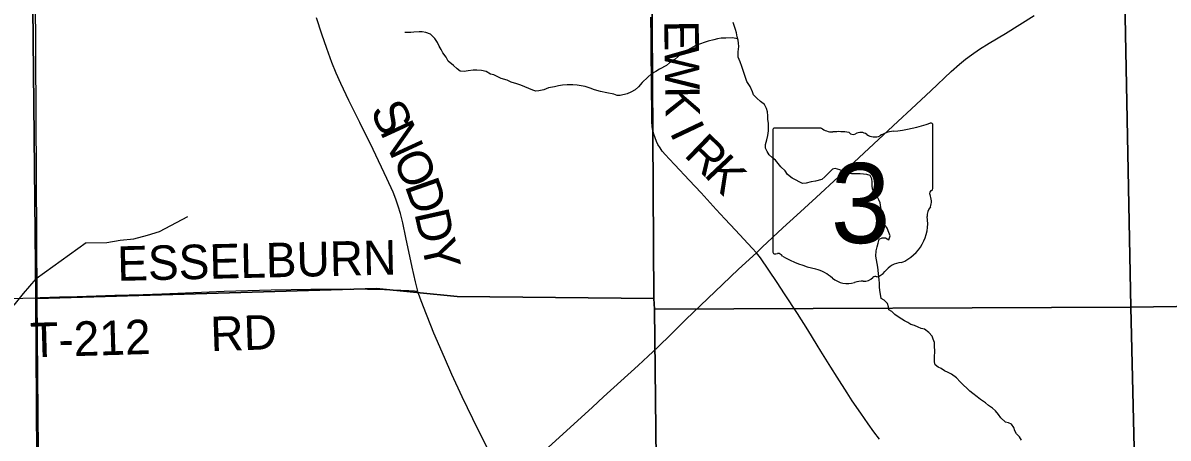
# Model space of a CAD drawing. Extents: x 0 to 34, y 0 to 22.
# Drawn here: x 2.612 to 4.5, y 16.137 to 16.821 of the extents above; entities that cross this region are included whole.
import ezdxf

# ---------------------------------------------------------------- set-up
doc = ezdxf.new("R2010")
doc.units = 0
for name, color, linetype in [('Default', 7, 'Continuous'), ('GM_X_County_Road', 7, 'Continuous'), ('GM_X_County_Road_Text', 7, 'Continuous'), ('GM_X_Minor_River', 7, 'Continuous'), ('GM_X_Section', 7, 'Continuous'), ('GM_X_State_Location', 7, 'Continuous'), ('GM_X_State_Route', 7, 'Continuous'), ('GM_X_State_Shield', 7, 'Continuous'), ('GM_X_Township_Road', 7, 'Continuous'), ('GM_X_Township_Road_Text', 7, 'Continuous'), ('SH_Cut_Line', 7, 'Continuous')]:
    doc.layers.add(name, color=color, linetype=linetype)

msp = doc.modelspace()

# ---------------------------------------------------------------- linework, layer by layer
at = {"layer": 'Default'}
msp.add_lwpolyline([(2.1, 18.375), (2.1, 14.3539), (2.1651, 14.3567), (2.6607, 14.3625), (2.6434, 15.3487), (2.6428, 15.3713), (2.6388, 15.4856), (2.6332, 16.3685), (2.6231, 17.3771), (2.6129, 17.8818), (2.6122, 18.05), (2.6118, 18.3803)], close=True, dxfattribs=at)
msp.add_lwpolyline([(2.6231, 17.3771), (2.6332, 16.3685), (2.6388, 15.4856), (2.6428, 15.3713), (2.6434, 15.3487), (2.6607, 14.3625), (2.7339, 14.3605), (3.1736, 14.3499), (3.5171, 14.3547), (3.6708, 14.3479), (4.282, 14.3483), (4.5209, 14.3512)], dxfattribs=at)
at = {"layer": 'GM_X_County_Road'}
for points in [[(3.8214, 16.4421), (3.8144, 16.4499), (3.7867, 16.4793), (3.7695, 16.498), (3.7549, 16.5134), (3.73, 16.541), (3.7106, 16.5619), (3.687, 16.5868), (3.6776, 16.5968), (3.6714, 16.6035), (3.6662, 16.6095), (3.6624, 16.6147), (3.6589, 16.6202), (3.6566, 16.6254), (3.6542, 16.6312), (3.6521, 16.6375), (3.6505, 16.6437), (3.6496, 16.6495), (3.6492, 16.659), (3.6488, 16.6745), (3.6485, 16.7118), (3.6484, 16.7367), (3.648, 16.7615), (3.6478, 16.7957), (3.6474, 16.8299)], [(4.0244, 16.135), (4.0151, 16.1474), (4.0058, 16.1603), (3.9932, 16.178), (3.9794, 16.1982), (3.9708, 16.2113), (3.9542, 16.2375), (3.9442, 16.2538), (3.9278, 16.2802), (3.9213, 16.2902), (3.9059, 16.3154), (3.889, 16.3419), (3.8676, 16.3747), (3.8555, 16.3931), (3.8282, 16.4336), (3.8236, 16.4395), (3.8214, 16.4421)], [(2.1, 16.3548), (2.1125, 16.3552), (2.1312, 16.3556), (2.1529, 16.3559), (2.2056, 16.3573), (2.2336, 16.3582), (2.2584, 16.3588), (2.3206, 16.3601), (2.3517, 16.3612), (2.4138, 16.3625), (2.4324, 16.363), (2.4665, 16.364), (2.4789, 16.3645), (2.4882, 16.3648), (2.5006, 16.3652), (2.5439, 16.3662), (2.5719, 16.3668), (2.5936, 16.3671), (2.6122, 16.3676), (2.6335, 16.3679)]]:
    msp.add_lwpolyline(points, dxfattribs=at)
at = {"layer": 'GM_X_Minor_River'}
for points in [[(3.9293, 16.5629), (3.9187, 16.5598), (3.9114, 16.5587), (3.9034, 16.5568), (3.8973, 16.556), (3.8919, 16.5587), (3.887, 16.5617), (3.8805, 16.5648), (3.8725, 16.5709), (3.869, 16.577), (3.8614, 16.5838), (3.8529, 16.5948), (3.848, 16.5986), (3.8426, 16.6032), (3.8388, 16.6089), (3.8365, 16.6146), (3.8365, 16.6207), (3.8384, 16.6283), (3.8399, 16.6352), (3.8414, 16.6431), (3.8413, 16.6549), (3.8402, 16.6622), (3.8402, 16.6675), (3.8398, 16.6743), (3.8382, 16.68), (3.8348, 16.6861), (3.8283, 16.6911), (3.8218, 16.6968), (3.8168, 16.7025), (3.8149, 16.7074), (3.8111, 16.7158), (3.8053, 16.7242), (3.8015, 16.7359), (3.7972, 16.7489), (3.7945, 16.7565), (3.7915, 16.7645), (3.7915, 16.7732), (3.7922, 16.7816), (3.7918, 16.7873), (3.7914, 16.7922), (3.7895, 16.7979), (3.7887, 16.8044), (3.7868, 16.8097), (3.7852, 16.815), (3.7829, 16.8215)], [(3.7906, 16.7946), (3.7811, 16.796), (3.7708, 16.7957), (3.7632, 16.7953), (3.7571, 16.7945), (3.7513, 16.7926), (3.7418, 16.7907), (3.7353, 16.7885), (3.7292, 16.7862), (3.7212, 16.7835), (3.7075, 16.7759), (3.7014, 16.7717), (3.693, 16.7657), (3.6869, 16.7603), (3.6782, 16.755), (3.6732, 16.7505), (3.6614, 16.7444), (3.6553, 16.7406), (3.6484, 16.7368), (3.6423, 16.7315), (3.6332, 16.7223), (3.6267, 16.7155), (3.6214, 16.7106), (3.6145, 16.7064), (3.6081, 16.7037), (3.597, 16.7011), (3.592, 16.7011), (3.5863, 16.7034), (3.5749, 16.7056), (3.5642, 16.7079), (3.5546, 16.7106), (3.547, 16.7133), (3.539, 16.7159), (3.526, 16.7182), (3.5187, 16.7186), (3.5096, 16.7186), (3.5019, 16.7179), (3.4951, 16.7171), (3.4882, 16.7156), (3.4787, 16.7137), (3.471, 16.7106), (3.4626, 16.7087), (3.4577, 16.7084), (3.4527, 16.7099), (3.4462, 16.7129), (3.4332, 16.7179), (3.4264, 16.7206), (3.4168, 16.7232), (3.4107, 16.7263), (3.4008, 16.7289), (3.3939, 16.7327), (3.3886, 16.735), (3.3828, 16.7365), (3.3759, 16.7404), (3.3679, 16.7423), (3.3607, 16.743), (3.3546, 16.7426), (3.3462, 16.7419), (3.3397, 16.7404), (3.3332, 16.7411), (3.3282, 16.7453), (3.3217, 16.7503), (3.3133, 16.7579), (3.3099, 16.7643), (3.3045, 16.7712), (3.3018, 16.7769), (3.2984, 16.7826), (3.2957, 16.7883), (3.2911, 16.7952), (3.2838, 16.802), (3.2762, 16.805), (3.2705, 16.8058), (3.2651, 16.8058), (3.2567, 16.8054), (3.2514, 16.8051), (3.2464, 16.8051), (3.2415, 16.8051)], [(4.2585, 16.1334), (4.2551, 16.1391), (4.2501, 16.144), (4.2474, 16.149), (4.2455, 16.1543), (4.2421, 16.1596), (4.2367, 16.1623), (4.2318, 16.163), (4.2245, 16.1703), (4.2203, 16.176), (4.2153, 16.1817), (4.2103, 16.1862), (4.2042, 16.1908), (4.1989, 16.195), (4.1905, 16.2007), (4.1855, 16.2049), (4.1782, 16.2102), (4.1729, 16.214), (4.1683, 16.219), (4.1629, 16.2243), (4.1572, 16.2296), (4.1511, 16.2361), (4.143, 16.2422), (4.1373, 16.2452), (4.1316, 16.2479), (4.1258, 16.2517), (4.1209, 16.2536), (4.1159, 16.2574), (4.1147, 16.2624), (4.1147, 16.2707), (4.1155, 16.2795), (4.1151, 16.2886), (4.1147, 16.2943), (4.1128, 16.2996), (4.1108, 16.3046), (4.1055, 16.311), (4.0982, 16.3164), (4.0932, 16.3175), (4.0879, 16.3194), (4.0822, 16.3221), (4.0757, 16.324), (4.0707, 16.3274), (4.0657, 16.3301), (4.0566, 16.3354), (4.0497, 16.3407), (4.0447, 16.3453), (4.0394, 16.3483), (4.039, 16.3533), (4.0374, 16.3586), (4.0321, 16.3643), (4.0271, 16.3666), (4.0259, 16.3738), (4.0248, 16.3799), (4.024, 16.386), (4.024, 16.3921), (4.0236, 16.3974), (4.0232, 16.4027), (4.0224, 16.4077), (4.022, 16.4137), (4.0213, 16.4187), (4.0205, 16.4244), (4.0182, 16.4366), (4.0189, 16.4453), (4.0204, 16.4518), (4.0223, 16.4582), (4.0238, 16.4647), (4.0288, 16.467), (4.0341, 16.4666), (4.0399, 16.4635), (4.0418, 16.47), (4.0398, 16.4757), (4.0371, 16.4826), (4.0329, 16.4879), (4.0299, 16.494), (4.0287, 16.5004), (4.0279, 16.5084), (4.0264, 16.5168), (4.0252, 16.5244), (4.0229, 16.5293), (4.0202, 16.5347), (4.0156, 16.5415), (4.0129, 16.5468), (4.0122, 16.5529), (4.0122, 16.5586), (4.0118, 16.564), (4.0087, 16.5693), (4.0034, 16.5712), (3.9976, 16.5716), (3.9923, 16.5719), (3.985, 16.572), (3.9782, 16.5723), (3.9713, 16.5735), (3.9656, 16.5754), (3.9591, 16.5788), (3.9514, 16.5807), (3.9465, 16.58), (3.9411, 16.5746), (3.9343, 16.567), (3.9293, 16.5629)], [(2.7164, 16.4585), (2.7503, 16.4588), (2.7723, 16.4627), (2.795, 16.4651), (2.8173, 16.4712), (2.8374, 16.4774), (2.8842, 16.5018)], [(2.7164, 16.4585), (2.634, 16.3993)], [(2.5979, 16.3559), (2.613, 16.3749), (2.634, 16.3993)]]:
    msp.add_lwpolyline(points, dxfattribs=at)
at = {"layer": 'GM_X_Section'}
for points in [[(2.6299, 17.3724), (3.6458, 17.376), (3.6462, 17.3555), (3.6522, 16.3668), (3.3278, 16.3702), (3.1951, 16.3831), (2.6357, 16.367)], [(4.419, 17.3654), (5.4312, 17.3835), (5.4444, 16.3706), (5.3035, 16.3654), (4.4387, 16.3528)], [(3.6462, 17.3555), (4.419, 17.3654), (4.4387, 16.3528), (3.6534, 16.349), (3.6522, 16.3668)], [(2.6357, 16.367), (3.1951, 16.3831), (3.3278, 16.3702), (3.6522, 16.3668), (3.6534, 16.349), (3.6643, 15.3607), (2.6446, 15.3609)], [(4.4387, 16.3528), (5.3035, 16.3654), (5.4444, 16.3706), (5.4966, 15.3772), (5.3765, 15.3766), (4.4621, 15.354)], [(3.6534, 16.349), (4.4387, 16.3528), (4.4621, 15.354), (3.6656, 15.3395), (3.6643, 15.3607)]]:
    msp.add_lwpolyline(points, close=True, dxfattribs=at)
at = {"layer": 'GM_X_State_Route'}
msp.add_lwpolyline([(3.4362, 16.0833), (3.4959, 16.1377), (3.5511, 16.1878), (3.5695, 16.2049), (3.6264, 16.2567), (3.6427, 16.2717), (3.6586, 16.2865), (3.6808, 16.3081), (3.7051, 16.3321), (3.7656, 16.39), (3.792, 16.4152), (3.8214, 16.4421), (3.8309, 16.4514), (3.865, 16.483), (3.8877, 16.5038), (3.9196, 16.5333), (3.9566, 16.5672), (3.9725, 16.582), (3.9906, 16.599), (4.0542, 16.6582), (4.0769, 16.6793), (4.1087, 16.7089), (4.1424, 16.7406), (4.1562, 16.753), (4.1658, 16.7611), (4.1758, 16.7681), (4.189, 16.7773), (4.2052, 16.7873), (4.2319, 16.8035), (4.2791, 16.8329)], dxfattribs=at)
at = {"layer": 'GM_X_State_Shield'}
for p, q in [((4.1121, 16.5478), (4.1121, 16.6525)), ((3.8484, 16.6441), (3.8484, 16.444)), ((3.9282, 16.6476), (3.851, 16.6476)), ((4.112, 16.5479), (4.1121, 16.5478))]:
    msp.add_line(p, q, dxfattribs=at)
for centre, radius, start, end in [((4.0181, 16.9204), 0.2796, 275.8445, 288.9065), ((4.1091, 16.653), 0.00294, 351.8621, 97.738), ((3.8514, 16.6446), 0.00305, 98.1301, 188.1301), ((3.9466, 16.6708), 0.0296, 231.6195, 271.1119), ((3.9564, 16.5352), 0.1064, 80.4867, 94.9883), ((3.9806, 16.6456), 0.00855, 219.7921, 297.1024), ((3.9931, 16.6225), 0.0178, 54.4667, 119.1411), ((4.0161, 16.6542), 0.0214, 233.8562, 294.8282), ((4.0538, 16.5865), 0.0563, 97.3462, 120.7689), ((4.1114, 16.5402), 0.00454, 107.944, 210.337), ((4.0825, 16.5269), 0.0273, 340.033, 23.6496), ((4.1089, 16.5474), 0.00314, 289.6038, 7.7341), ((4.0338, 16.4907), 0.0699, 292.3089, 8.9858), ((4.1226, 16.504), 0.0198, 136.8065, 186.9296), ((3.8514, 16.4436), 0.00308, 171.9584, 258.3066), ((3.8519, 16.464), 0.0235, 267.339, 280.6039), ((3.8567, 16.4325), 0.00848, 29.7484, 93.2717), ((3.9638, 16.6123), 0.2019, 240.4129, 257.1985), ((4.0633, 16.3878), 0.0383, 94.4031, 142.5768), ((3.9036, 16.3541), 0.0632, 47.1842, 75.836), ((4.0148, 16.4246), 0.0226, 282.8732, 323.2771), ((3.9719, 16.4315), 0.0401, 230.7004, 286.2918), ((3.9951, 16.3623), 0.0329, 85.6951, 111.2099), ((3.998, 16.4165), 0.0214, 268.777, 315.5493), ((4.0173, 16.3971), 0.00601, 65.7517, 132.6484)]:
    msp.add_arc(centre, radius, start, end, dxfattribs=at)
at = {"layer": 'GM_X_Township_Road'}
for points in [[(3.2633, 16.379), (3.2593, 16.3945), (3.2537, 16.4187), (3.2434, 16.4674), (3.2383, 16.4917), (3.2346, 16.5068), (3.231, 16.5187), (3.2269, 16.5304), (3.2223, 16.5419), (3.2119, 16.5645), (3.1893, 16.6122), (3.1675, 16.6569), (3.1495, 16.6931), (3.1361, 16.7211), (3.1285, 16.7381), (3.1215, 16.7554), (3.1129, 16.7787), (3.105, 16.8023), (3.0964, 16.8289)], [(2.6335, 16.3679), (2.6408, 16.3682), (2.6725, 16.3693), (2.7017, 16.3703), (2.7638, 16.3722), (2.8104, 16.3734), (2.8414, 16.3746), (2.9066, 16.3773), (2.9439, 16.3788), (3.0215, 16.3811), (3.0868, 16.3824), (3.1521, 16.3828), (3.1801, 16.3823), (3.2081, 16.3814), (3.2484, 16.3798), (3.2577, 16.3793), (3.2633, 16.379)], [(3.4093, 16.0586), (3.3971, 16.0824), (3.3803, 16.1156), (3.354, 16.1685), (3.3365, 16.2049), (3.3195, 16.2415), (3.3069, 16.2699), (3.2898, 16.3099), (3.2723, 16.3531), (3.2668, 16.3676), (3.264, 16.3765), (3.2633, 16.379)]]:
    msp.add_lwpolyline(points, dxfattribs=at)
at = {"layer": 'SH_Cut_Line'}
msp.add_lwpolyline([(2.6032, 20.9), (2.1, 20.9), (2.1, 14.3539), (2.1651, 14.3567), (2.6607, 14.3625), (2.6434, 15.3487), (2.6428, 15.3713), (2.6388, 15.4856), (2.6332, 16.3685), (2.6231, 17.3771), (2.6129, 17.8818), (2.6122, 18.05), (2.6118, 18.3803), (2.6161, 18.3799), (2.6204, 18.3797), (2.6263, 18.3795), (2.6292, 18.3794), (2.6281, 18.8843), (2.6224, 19.9515), (2.6032, 20.8721)], close=True, dxfattribs=at)
msp.add_lwpolyline([(2.6231, 17.3771), (2.6332, 16.3685), (2.6388, 15.4856), (2.6428, 15.3713), (2.6434, 15.3487), (2.6607, 14.3625), (2.7339, 14.3605), (3.1736, 14.3499), (3.5171, 14.3547), (3.6708, 14.3479), (4.282, 14.3483), (4.5209, 14.3512)], dxfattribs=at)

# ---------------------------------------------------------------- texts
at = {"layer": 'GM_X_County_Road_Text'}
for s, rotation, p in [('E', 270.8357, (3.6693, 16.8245)), ('W', 270.8368, (3.6699, 16.782)), ('K', 270.8539, (3.6709, 16.7161)), ('I', 295.3529, (3.6775, 16.6409)), ('R', 315.9278, (3.7002, 16.6021)), ('K', 313.2907, (3.7332, 16.5702))]:
    msp.add_text(s, height=0.0568, rotation=rotation, dxfattribs=at).set_placement(p)
at = {"layer": 'GM_X_State_Location'}
for s in ['s', 'r']:
    msp.add_text(s, height=0.000189, dxfattribs=at).set_placement((3.9773, 16.5308))
msp.add_text('3', height=0.000189, rotation=0, dxfattribs=at).set_placement((3.9487, 16.517))
at = {"layer": 'GM_X_State_Shield'}
msp.add_text('3', height=0.1318, dxfattribs=at).set_placement((3.9441, 16.4581))
at = {"layer": 'GM_X_Township_Road_Text'}
for s, height, rotation, p in [('S', 0.0568, 294.7139, (3.1839, 16.6771)), ('N', 0.0568, 294.7154, (3.2, 16.6423)), ('O', 0.0568, 294.6261, (3.2208, 16.5969)), ('D', 0.0568, 289.3445, (3.2412, 16.5528)), ('D', 0.0568, 282.6464, (3.2572, 16.5073)), ('ESSELBURN', 0.05682, 1.3128, (2.7682, 16.3958)), ('Y', 0.0568, 282.6013, (3.2682, 16.4585)), ('T-212', 0.05682, 1.6682, (2.625, 16.2698)), ('RD', 0.05682, 1.9421, (2.922, 16.2799))]:
    msp.add_text(s, height=height, rotation=rotation, dxfattribs=at).set_placement(p)

doc.saveas('drawing.dxf')
